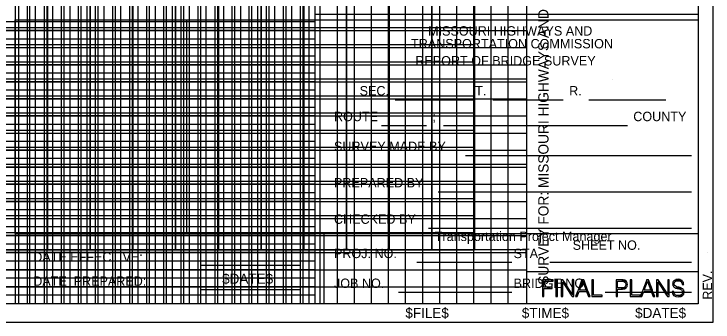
# Model space of a CAD drawing. Extents: x 0 to 31.6, y 0 to 20.8.
# Drawn here: x 23.41 to 31.6, y 0 to 3.61 of the extents above; entities that cross this region are included whole.
import ezdxf

# ---------------------------------------------------------------- set-up
doc = ezdxf.new("R2010")
doc.units = 0
for name, color, linetype in [('Border-Border', 7, 'Continuous'), ('Border-Bridge survey title block', 7, 'Continuous'), ('Border-Bridge xsection major grid lines', 7, 'Continuous'), ('Border-Bridge xsection minor grid lines', 7, 'Continuous'), ('Border-Construction Final Plans Stamp', 7, 'Continuous'), ('Border-Date stamp', 7, 'Continuous'), ('Border-File stamp', 7, 'Continuous'), ('Border-Full plan shape', 7, 'Continuous'), ('Border-Full profile major grid lines', 7, 'Continuous'), ('Border-Full profile minor grid lines', 7, 'Continuous'), ('Border-Full profile shape', 7, 'Continuous'), ('Border-Full xsection major grid lines', 7, 'Continuous'), ('Border-Full xsection minor grid lines', 7, 'Continuous'), ('Border-Plan bottom shape', 7, 'Continuous'), ('Border-Plan-profile major grid lines', 7, 'Continuous'), ('Border-Plan-profile minor grid lines', 7, 'Continuous'), ('Border-Plotting block', 7, 'Continuous'), ('Border-Profile bottom shape', 7, 'Continuous'), ('Border-Revision note', 7, 'Continuous'), ('Border-Time stamp', 7, 'Continuous'), ('Border-Title block - Final Plans Consultant Manual Seal', 7, 'Continuous'), ('Border-Title block - Final Plans Electronic Seal', 7, 'Continuous'), ('Border-Title block - Location Survey Electronic Seal', 7, 'Continuous'), ('Border-Title block - Standard Plans Electronic Seal', 7, 'Continuous'), ('Border-Xsection shape', 7, 'Continuous')]:
    doc.layers.add(name, color=color, linetype=linetype)

msp = doc.modelspace()

# ---------------------------------------------------------------- linework, layer by layer
at = {"layer": 'Border-Border'}
for p, q in [((31.425, 20.5875), (31.425, 0.2125)), ((31.425, 0.2125), (0.175, 0.2125)), ((31.5999, 0), (31.5999, 0))]:
    msp.add_line(p, q, dxfattribs=at)
at = {"layer": 'Border-Bridge survey title block'}
for p, q in [((26.9414, 3.6031), (31.4249, 3.6031)), ((27.8783, 2.6015), (28.7934, 2.6015)), ((29.02, 2.6015), (29.8454, 2.6015)), ((30.1465, 2.6015), (31.047, 2.6015)), ((27.7184, 2.3007), (28.2439, 2.3007)), ((28.4439, 2.3007), (30.5966, 2.3007)), ((28.7003, 1.9511), (31.3478, 1.9511)), ((28.3806, 1.5251), (31.3478, 1.5251)), ((28.2664, 1.0991), (31.3478, 1.0991)), ((28.1294, 0.6991), (29.2454, 0.6991)), ((29.6898, 0.6991), (31.3478, 0.6991)), ((27.9164, 0.3479), (29.2454, 0.3479)), ((30.3368, 0.3479), (31.3478, 0.3479))]:
    msp.add_line(p, q, dxfattribs=at)
msp.add_lwpolyline([(26.9414, 0.2125), (26.9414, 4.2047), (31.4249, 4.2047)], dxfattribs=at)
at = {"layer": 'Border-Bridge xsection major grid lines'}
for p, q in [((23.665, 0.2125), (23.665, 20.5875)), ((24.665, 0.2125), (24.665, 20.5875)), ((25.6649, 0.2125), (25.6649, 20.5875)), ((26.6649, 0.2125), (26.6649, 20.5875)), ((0.175, 3.2125), (26.9415, 3.2125)), ((0.175, 2.2125), (26.9415, 2.2125)), ((0.175, 1.2125), (26.9415, 1.2125))]:
    msp.add_line(p, q, dxfattribs=at)
at = {"layer": 'Border-Bridge xsection minor grid lines'}
for p, q in [((23.465, 20.5875), (23.465, 0.2125)), ((23.565, 20.5875), (23.565, 0.2125)), ((23.765, 20.5875), (23.765, 0.2125)), ((23.865, 20.5875), (23.865, 0.2125)), ((23.965, 20.5875), (23.965, 0.2125)), ((24.065, 20.5875), (24.065, 0.2125)), ((24.165, 20.5875), (24.165, 0.2125)), ((24.265, 20.5875), (24.265, 0.2125)), ((24.365, 20.5875), (24.365, 0.2125)), ((24.465, 20.5875), (24.465, 0.2125)), ((24.565, 20.5875), (24.565, 0.2125)), ((24.765, 20.5875), (24.765, 0.2125)), ((24.865, 20.5875), (24.865, 0.2125)), ((24.965, 20.5875), (24.965, 0.2125)), ((25.0649, 20.5875), (25.0649, 0.2125)), ((25.1649, 20.5875), (25.1649, 0.2125)), ((25.2649, 20.5875), (25.2649, 0.2125)), ((25.3649, 20.5875), (25.3649, 0.2125)), ((25.4649, 20.5875), (25.4649, 0.2125)), ((25.5649, 20.5875), (25.5649, 0.2125)), ((25.7649, 20.5875), (25.7649, 0.2125)), ((25.8649, 20.5875), (25.8649, 0.2125)), ((25.9649, 20.5875), (25.9649, 0.2125)), ((26.0649, 20.5875), (26.0649, 0.2125)), ((26.1649, 20.5875), (26.1649, 0.2125)), ((26.2649, 20.5875), (26.2649, 0.2125)), ((26.3649, 20.5875), (26.3649, 0.2125)), ((26.4649, 20.5875), (26.4649, 0.2125)), ((26.5649, 20.5875), (26.5649, 0.2125)), ((26.7649, 20.5875), (26.7649, 0.2125)), ((26.8649, 20.5875), (26.8649, 0.2125)), ((26.9415, 3.5125), (0.175, 3.5125)), ((26.9415, 3.4125), (0.175, 3.4125)), ((26.9415, 3.3125), (0.175, 3.3125)), ((26.9415, 3.1125), (0.175, 3.1125)), ((26.9415, 3.0125), (0.175, 3.0125)), ((26.9415, 2.9125), (0.175, 2.9125)), ((26.9415, 2.8125), (0.175, 2.8125)), ((26.9415, 2.7125), (0.175, 2.7125)), ((26.9415, 2.6125), (0.175, 2.6125)), ((26.9415, 2.5125), (0.175, 2.5125)), ((26.9415, 2.4125), (0.175, 2.4125)), ((26.9415, 2.3125), (0.175, 2.3125)), ((26.9415, 2.1125), (0.175, 2.1125)), ((26.9415, 2.0125), (0.175, 2.0125)), ((26.9415, 1.9125), (0.175, 1.9125)), ((26.9415, 1.8125), (0.175, 1.8125)), ((26.9415, 1.7125), (0.175, 1.7125)), ((26.9415, 1.6125), (0.175, 1.6125)), ((26.9415, 1.5125), (0.175, 1.5125)), ((26.9415, 1.4125), (0.175, 1.4125)), ((26.9415, 1.3125), (0.175, 1.3125)), ((26.9415, 1.1125), (0.175, 1.1125)), ((26.9415, 1.0125), (0.175, 1.0125)), ((26.9415, 0.9125), (0.175, 0.9125)), ((26.9415, 0.8125), (0.175, 0.8125)), ((26.9415, 0.7125), (0.175, 0.7125)), ((26.9415, 0.6125), (0.175, 0.6125)), ((26.9415, 0.5125), (0.175, 0.5125)), ((26.9415, 0.4125), (0.175, 0.4125)), ((26.9415, 0.3125), (0.175, 0.3125))]:
    msp.add_line(p, q, dxfattribs=at)
at = {"layer": 'Border-Construction Final Plans Stamp'}
msp.add_line((29.4171, 0.5925), (31.4249, 0.5925), dxfattribs=at)
for points in [[(29.6017, 0.3913), (29.6017, 0.2983), (29.6199, 0.2983), (29.6199, 0.3913), (29.716, 0.3913), (29.716, 0.4074), (29.6199, 0.4074), (29.6199, 0.4783), (29.7258, 0.4783), (29.7258, 0.4943), (29.6017, 0.4943), (29.6017, 0.4783), (29.6017, 0.4074)], [(29.758, 0.4943), (29.758, 0.2983), (29.7765, 0.2983), (29.7765, 0.4943)], [(29.8215, 0.3262), (29.8215, 0.2983), (29.8392, 0.2983), (29.8392, 0.3262), (29.8392, 0.4665), (29.8596, 0.4665), (29.8414, 0.4943), (29.8215, 0.4943), (29.8215, 0.4665)], [(29.952, 0.4943), (29.952, 0.3262), (29.9697, 0.3262), (29.9697, 0.4943)], [(30.0132, 0.3587), (29.9903, 0.2983), (30.009, 0.2983), (30.0315, 0.3587), (30.1377, 0.3587), (30.1317, 0.3744), (30.0373, 0.3744), (30.0754, 0.4754), (30.0933, 0.4754), (30.0862, 0.4943), (30.0647, 0.4943), (30.0575, 0.4754), (30.0192, 0.3744)], [(30.1813, 0.3143), (30.1813, 0.2983), (30.3, 0.2983), (30.3, 0.3143), (30.1998, 0.3143), (30.1998, 0.4943), (30.1813, 0.4943)], [(30.4647, 0.3834), (30.4647, 0.2983), (30.4828, 0.2983), (30.4828, 0.3834), (30.5245, 0.3834), (30.5391, 0.3839), (30.5619, 0.3879), (30.5812, 0.3987), (30.582, 0.3998), (30.4828, 0.3998), (30.4828, 0.3999), (30.4828, 0.4015), (30.4828, 0.4086), (30.4828, 0.4168), (30.4828, 0.4228), (30.4828, 0.4394), (30.4828, 0.4396), (30.4828, 0.4557), (30.4828, 0.4598), (30.4828, 0.4682), (30.4828, 0.4757), (30.4828, 0.4774), (30.4828, 0.4779), (30.4828, 0.4783), (30.5834, 0.4783), (30.5671, 0.4893), (30.5474, 0.4937), (30.5333, 0.4943), (30.4647, 0.4943), (30.4647, 0.4937), (30.4647, 0.4893), (30.4647, 0.4783), (30.4647, 0.4779), (30.4647, 0.4774), (30.4647, 0.4757), (30.4647, 0.4682), (30.4647, 0.4598), (30.4647, 0.4557), (30.4647, 0.4396), (30.4647, 0.4394), (30.4647, 0.4228), (30.4647, 0.4168), (30.4647, 0.4086), (30.4647, 0.4015), (30.4647, 0.3999), (30.4647, 0.3998), (30.4647, 0.3987), (30.4647, 0.3879), (30.4647, 0.3839)], [(30.6295, 0.3143), (30.6295, 0.2983), (30.7482, 0.2983), (30.7482, 0.3143), (30.648, 0.3143), (30.648, 0.4943), (30.6295, 0.4943)], [(30.7711, 0.3587), (30.7482, 0.2983), (30.7669, 0.2983), (30.7894, 0.3587), (30.8956, 0.3587), (30.8896, 0.3744), (30.7952, 0.3744), (30.8333, 0.4754), (30.8512, 0.4754), (30.8441, 0.4943), (30.8226, 0.4943), (30.8154, 0.4754), (30.7771, 0.3744)], [(30.9392, 0.3262), (30.9392, 0.2983), (30.9569, 0.2983), (30.9569, 0.3262), (30.9569, 0.4665), (30.9774, 0.4665), (30.9591, 0.4943), (30.9392, 0.4943), (30.9392, 0.4665)], [(31.0697, 0.4943), (31.0697, 0.3262), (31.0874, 0.3262), (31.0874, 0.4943)], [(31.1443, 0.4851), (31.1434, 0.4846), (31.2378, 0.4846), (31.2374, 0.4851), (31.2175, 0.4957), (31.2149, 0.4961), (31.1643, 0.4961), (31.1636, 0.4957)], [(31.1906, 0.4997), (31.1643, 0.4961), (31.2149, 0.4961)], [(29.9314, 0.3262), (29.9498, 0.2983), (29.9697, 0.2983), (29.9697, 0.3262), (29.952, 0.3262), (29.8597, 0.4665), (29.8392, 0.4665)], [(30.0754, 0.4754), (30.1135, 0.3744), (30.1317, 0.3744), (30.0934, 0.4754)], [(30.5324, 0.4783), (30.5394, 0.4779), (30.5839, 0.4779), (30.5834, 0.4783)], [(30.5657, 0.4086), (30.5497, 0.4015), (30.5831, 0.4015), (30.588, 0.4086), (30.5936, 0.4168), (30.5947, 0.4228), (30.5946, 0.4228), (30.5976, 0.4394), (30.5976, 0.4396), (30.5954, 0.4557), (30.5949, 0.4598), (30.59, 0.4682), (30.5856, 0.4757), (30.5846, 0.4774), (30.5839, 0.4779), (30.5394, 0.4779), (30.5428, 0.4774), (30.5544, 0.4757), (30.5686, 0.4682), (30.5741, 0.4598), (30.5767, 0.4557), (30.5791, 0.4396), (30.5791, 0.4394), (30.5762, 0.4228), (30.5718, 0.4168)], [(30.8333, 0.4754), (30.8714, 0.3744), (30.8896, 0.3744), (30.8513, 0.4754)], [(31.0492, 0.3262), (31.0675, 0.2983), (31.0874, 0.2983), (31.0874, 0.3262), (31.0697, 0.3262), (30.9774, 0.4665), (30.9569, 0.4665)], [(31.1654, 0.3978), (31.1677, 0.3969), (31.2311, 0.3969), (31.2296, 0.3978), (31.2145, 0.4031), (31.2144, 0.4031), (31.2128, 0.4037), (31.2007, 0.4071), (31.1779, 0.4129), (31.1752, 0.4137), (31.1671, 0.4161), (31.1548, 0.4228), (31.1503, 0.4286), (31.1471, 0.4328), (31.1457, 0.4397), (31.1445, 0.4462), (31.1445, 0.4464), (31.1445, 0.4469), (31.1446, 0.4474), (31.1467, 0.4596), (31.1469, 0.4611), (31.151, 0.4668), (31.1515, 0.4674), (31.1515, 0.4674), (31.1551, 0.4724), (31.1555, 0.473), (31.1703, 0.481), (31.1709, 0.4814), (31.1897, 0.4836), (31.2385, 0.4836), (31.2378, 0.4846), (31.1434, 0.4846), (31.1427, 0.4836), (31.141, 0.4814), (31.1408, 0.481), (31.135, 0.473), (31.1346, 0.4724), (31.1309, 0.4674), (31.1305, 0.4668), (31.1294, 0.4611), (31.1291, 0.4596), (31.1267, 0.4474), (31.1266, 0.4469), (31.1267, 0.4464), (31.1267, 0.4462), (31.1276, 0.4397), (31.1286, 0.4328), (31.1292, 0.4286), (31.1325, 0.4228), (31.1365, 0.4161), (31.1379, 0.4137), (31.139, 0.4129), (31.1464, 0.4071), (31.1508, 0.4037), (31.1515, 0.4031)], [(31.238, 0.4462), (31.2384, 0.4397), (31.2565, 0.4397), (31.2561, 0.4462), (31.2561, 0.4464), (31.2561, 0.4469), (31.2561, 0.4474), (31.2528, 0.4596), (31.2528, 0.4596), (31.2524, 0.4611), (31.2509, 0.4668), (31.2507, 0.4674), (31.2469, 0.4724), (31.2465, 0.473), (31.2404, 0.481), (31.2402, 0.4814), (31.2402, 0.4814), (31.2385, 0.4836), (31.1897, 0.4836), (31.2063, 0.4814), (31.2086, 0.481), (31.2239, 0.473), (31.225, 0.4724), (31.2287, 0.4674), (31.2291, 0.4668), (31.2332, 0.4611), (31.2343, 0.4596), (31.2377, 0.4474), (31.2378, 0.4469), (31.2379, 0.4464)], [(30.1194, 0.3587), (30.1418, 0.2983), (30.1606, 0.2983), (30.1377, 0.3587)], [(30.5323, 0.3999), (30.5248, 0.3998), (30.582, 0.3998), (30.582, 0.3999)], [(30.5496, 0.4015), (30.5324, 0.3999), (30.582, 0.3999), (30.5831, 0.4015)], [(30.8772, 0.3587), (30.8997, 0.2983), (30.9185, 0.2983), (30.8956, 0.3587)], [(31.1647, 0.2968), (31.1947, 0.293), (31.2202, 0.2968), (31.224, 0.2974), (31.2444, 0.309), (31.195, 0.309), (31.1924, 0.3093), (31.186, 0.3101), (31.1753, 0.3113), (31.174, 0.3119), (31.1585, 0.3186), (31.1553, 0.3221), (31.1498, 0.3279), (31.1498, 0.3279), (31.1471, 0.3308), (31.1459, 0.3322), (31.1442, 0.337), (31.1408, 0.3468), (31.1404, 0.3502), (31.1403, 0.3517), (31.1398, 0.3577), (31.1217, 0.3577), (31.1219, 0.3517), (31.122, 0.3502), (31.1227, 0.3468), (31.1246, 0.337), (31.1255, 0.3322), (31.1258, 0.3308), (31.1278, 0.3279), (31.1319, 0.3221), (31.1343, 0.3186), (31.139, 0.3119), (31.1395, 0.3113), (31.1403, 0.3101), (31.1409, 0.3093), (31.1415, 0.309), (31.1636, 0.2974)], [(31.1974, 0.3093), (31.195, 0.309), (31.2444, 0.309), (31.2449, 0.3093), (31.2462, 0.3101), (31.2471, 0.3113), (31.2475, 0.3119), (31.2521, 0.3186), (31.2545, 0.3221), (31.2585, 0.3279), (31.2589, 0.3308), (31.2589, 0.3308), (31.2591, 0.3322), (31.2598, 0.337), (31.2613, 0.3468), (31.2618, 0.3502), (31.2621, 0.3517), (31.2592, 0.3661), (31.2579, 0.3723), (31.2541, 0.3771), (31.2484, 0.3846), (31.2458, 0.3879), (31.2439, 0.3891), (31.2439, 0.3891), (31.2361, 0.3938), (31.2311, 0.3969), (31.1677, 0.3969), (31.1796, 0.3938), (31.1982, 0.3891), (31.2022, 0.3879), (31.2142, 0.3846), (31.2302, 0.3771), (31.2346, 0.3723), (31.2402, 0.3661), (31.2438, 0.3517), (31.2437, 0.3502), (31.2434, 0.3468), (31.2427, 0.337), (31.2399, 0.3322), (31.2391, 0.3308), (31.2374, 0.3279), (31.2341, 0.3221), (31.2281, 0.3186), (31.2166, 0.3119), (31.2124, 0.3113), (31.203, 0.3101)]]:
    msp.add_lwpolyline(points, close=True, dxfattribs=at)
at = {"layer": 'Border-Full plan shape'}
msp.add_lwpolyline([(0.8061, 19.9564), (28.8061, 19.9564), (28.8061, 0.8436), (0.8061, 0.8436)], close=True, dxfattribs=at)
at = {"layer": 'Border-Full profile major grid lines'}
for p, q in [((23.8061, 19.8436), (23.8061, 0.8436)), ((24.8061, 19.8436), (24.8061, 0.8436)), ((25.8061, 19.8436), (25.8061, 0.8436)), ((26.8061, 19.8436), (26.8061, 0.8436)), ((27.8061, 19.8436), (27.8061, 0.8436)), ((28.8061, 19.8436), (28.8061, 0.8436)), ((29.4171, 2.8436), (0.175, 2.8436)), ((29.4171, 1.8436), (0.175, 1.8436)), ((29.4171, 0.8436), (0.175, 0.8436))]:
    msp.add_line(p, q, dxfattribs=at)
at = {"layer": 'Border-Full profile minor grid lines'}
for p, q in [((24.3061, 19.8436), (24.3061, 0.8436)), ((25.3061, 19.8436), (25.3061, 0.8436)), ((26.3061, 19.8436), (26.3061, 0.8436)), ((27.3061, 19.8436), (27.3061, 0.8436)), ((28.3061, 19.8436), (28.3061, 0.8436)), ((28.8061, 3.4436), (0.8061, 3.4436)), ((28.8061, 3.2436), (0.8061, 3.2436)), ((28.8061, 3.0436), (0.8061, 3.0436)), ((28.8061, 2.6436), (0.8061, 2.6436)), ((28.8061, 2.4436), (0.8061, 2.4436)), ((28.8061, 2.2436), (0.8061, 2.2436)), ((28.8061, 2.0436), (0.8061, 2.0436)), ((28.8061, 1.6436), (0.8061, 1.6436)), ((28.8061, 1.4436), (0.8061, 1.4436)), ((28.8061, 1.2436), (0.8061, 1.2436)), ((28.8061, 1.0436), (0.8061, 1.0436))]:
    msp.add_line(p, q, dxfattribs=at)
at = {"layer": 'Border-Full profile shape'}
msp.add_lwpolyline([(0.8061, 19.9564), (28.8061, 19.9564), (28.8061, 0.8436), (0.8061, 0.8436)], close=True, dxfattribs=at)
at = {"layer": 'Border-Full xsection major grid lines'}
for p, q in [((23.8, 0.2125), (23.8, 20.5875)), ((24.8, 0.2125), (24.8, 20.5875)), ((25.7999, 0.2125), (25.7999, 20.5875)), ((26.7999, 0.2125), (26.7999, 20.5875)), ((27.7999, 0.2125), (27.7999, 20.5875)), ((28.7999, 0.2125), (28.7999, 20.5875)), ((0.175, 3.2125), (29.4171, 3.2125)), ((0.175, 2.2125), (29.4171, 2.2125)), ((0.175, 1.2125), (29.4171, 1.2125))]:
    msp.add_line(p, q, dxfattribs=at)
at = {"layer": 'Border-Full xsection minor grid lines'}
for p, q in [((23.6, 0.2125), (23.6, 20.5875)), ((24, 0.2125), (24, 20.5875)), ((24.2, 0.2125), (24.2, 20.5875)), ((24.4, 0.2125), (24.4, 20.5875)), ((24.6, 0.2125), (24.6, 20.5875)), ((24.9999, 0.2125), (24.9999, 20.5875)), ((25.1999, 0.2125), (25.1999, 20.5875)), ((25.3999, 0.2125), (25.3999, 20.5875)), ((25.5999, 0.2125), (25.5999, 20.5875)), ((25.9999, 0.2125), (25.9999, 20.5875)), ((26.1999, 0.2125), (26.1999, 20.5875)), ((26.3999, 0.2125), (26.3999, 20.5875)), ((26.5999, 0.2125), (26.5999, 20.5875)), ((26.9999, 0.2125), (26.9999, 20.5875)), ((27.1999, 0.2125), (27.1999, 20.5875)), ((27.3999, 0.2125), (27.3999, 20.5875)), ((27.5999, 0.2125), (27.5999, 20.5875)), ((27.9999, 0.2125), (27.9999, 20.5875)), ((28.1999, 0.2125), (28.1999, 20.5875)), ((28.3999, 0.2125), (28.3999, 20.5875)), ((28.5999, 0.2125), (28.5999, 20.5875)), ((28.9999, 0.2125), (28.9999, 20.5875)), ((29.1999, 0.2125), (29.1999, 20.5875)), ((0.175, 3.4125), (29.4171, 3.4125)), ((0.175, 3.0125), (29.4171, 3.0125)), ((0.175, 2.8125), (29.4171, 2.8125)), ((0.175, 2.6125), (29.4171, 2.6125)), ((0.175, 2.4125), (29.4171, 2.4125)), ((0.175, 2.0125), (29.4171, 2.0125)), ((0.175, 1.8125), (29.4171, 1.8125)), ((0.175, 1.6125), (29.4171, 1.6125)), ((0.175, 1.4125), (29.4171, 1.4125)), ((0.175, 1.0125), (29.4171, 1.0125)), ((0.175, 0.8125), (29.4171, 0.8125)), ((0.175, 0.6125), (29.4171, 0.6125)), ((0.175, 0.4125), (29.4171, 0.4125))]:
    msp.add_line(p, q, dxfattribs=at)
at = {"layer": 'Border-Plan bottom shape'}
msp.add_lwpolyline([(0.8061, 10.3253), (28.8061, 10.3253), (28.8061, 0.8436), (0.8061, 0.8436)], close=True, dxfattribs=at)
at = {"layer": 'Border-Plan-profile major grid lines'}
for p, q in [((23.8061, 0.8436), (23.8061, 9.8436)), ((24.8061, 0.8436), (24.8061, 9.8436)), ((25.8061, 0.8436), (25.8061, 9.8436)), ((26.8061, 0.8436), (26.8061, 9.8436)), ((27.8061, 0.8436), (27.8061, 9.8436)), ((28.8061, 0.8436), (28.8061, 9.8436)), ((29.4233, 2.8436), (0.1811, 2.8436)), ((29.4233, 1.8436), (0.1811, 1.8436)), ((29.4233, 0.8436), (0.1811, 0.8436))]:
    msp.add_line(p, q, dxfattribs=at)
at = {"layer": 'Border-Plan-profile minor grid lines'}
for p, q in [((24.3061, 0.8436), (24.3061, 9.8436)), ((25.3061, 0.8436), (25.3061, 9.8436)), ((26.3061, 0.8436), (26.3061, 9.8436)), ((27.3061, 0.8436), (27.3061, 9.8436)), ((28.3061, 0.8436), (28.3061, 9.8436)), ((28.8061, 3.4436), (0.8061, 3.4436)), ((28.8061, 3.2436), (0.8061, 3.2436)), ((28.8061, 3.0436), (0.8061, 3.0436)), ((28.8061, 2.6436), (0.8061, 2.6436)), ((28.8061, 2.4436), (0.8061, 2.4436)), ((28.8061, 2.2436), (0.8061, 2.2436)), ((28.8061, 2.0436), (0.8061, 2.0436)), ((28.8061, 1.6436), (0.8061, 1.6436)), ((28.8061, 1.4436), (0.8061, 1.4436)), ((28.8061, 1.2436), (0.8061, 1.2436)), ((28.8061, 1.0436), (0.8061, 1.0436))]:
    msp.add_line(p, q, dxfattribs=at)
at = {"layer": 'Border-Plotting block'}
msp.add_lwpolyline([(0, 0), (31.5999, 0), (31.5999, 20.8), (0, 20.8)], close=True, dxfattribs=at)
at = {"layer": 'Border-Profile bottom shape'}
msp.add_lwpolyline([(0.8061, 0.8436), (28.8061, 0.8436), (28.8061, 9.8436), (0.8061, 9.8436)], close=True, dxfattribs=at)
at = {"layer": 'Border-Revision note'}
msp.add_line((31.5347, 0.8092), (31.5347, 0.8092), dxfattribs=at)
at = {"layer": 'Border-Title block - Final Plans Consultant Manual Seal'}
msp.add_line((29.4171, 20.5875), (29.4171, 0.2125), dxfattribs=at)
at = {"layer": 'Border-Title block - Final Plans Electronic Seal'}
for p, q in [((29.4171, 20.5875), (29.4171, 0.2125)), ((30.4211, 2.8362), (30.4211, 2.8362))]:
    msp.add_line(p, q, dxfattribs=at)
at = {"layer": 'Border-Title block - Location Survey Electronic Seal'}
msp.add_line((29.4171, 20.5875), (29.4171, 0.2125), dxfattribs=at)
at = {"layer": 'Border-Title block - Standard Plans Electronic Seal'}
for p, q in [((23.4249, 4.8718), (23.4249, 0.2125)), ((23.4249, 3.5375), (31.425, 3.5375)), ((25.4328, 3.5375), (25.4328, 1.0375)), ((23.4249, 1.0375), (31.425, 1.0375)), ((27.0397, 1.0375), (27.0397, 0.2125)), ((29.4171, 1.0375), (29.4171, 0.2125)), ((25.6068, 0.6651), (26.7737, 0.6651)), ((25.6068, 0.3818), (26.7737, 0.3818))]:
    msp.add_line(p, q, dxfattribs=at)
msp.add_lwpolyline([(23.4249, 3.5375), (25.4328, 3.5375), (25.4328, 1.0375), (23.4249, 1.0375)], close=True, dxfattribs=at)
at = {"layer": 'Border-Xsection shape'}
msp.add_lwpolyline([(29.4171, 0.2125), (0.175, 0.2125), (0.175, 20.5875), (29.4171, 20.5875)], close=True, dxfattribs=at)

# ---------------------------------------------------------------- texts
at = {"layer": 'Border-Bridge survey title block'}
for s, height, p in [('MISSOURI HIGHWAYS AND', 0.110166, (28.2628, 3.3527)), ('TRANSPORTATION COMMISSION', 0.110192, (28.0628, 3.2031)), ('REPORT OF BRIDGE SURVEY', 0.110192, (28.1131, 3.0031)), ('SEC.', 0.11019, (27.4612, 2.6518)), ('T.', 0.11019, (28.8139, 2.6518)), ('R.', 0.11019, (29.9147, 2.6518)), ('ROUTE', 0.11019, (27.1604, 2.3511)), ('COUNTY', 0.11019, (30.6659, 2.3511)), (';', 0.1102, (28.3131, 2.3511)), ('SURVEY MADE BY', 0.110192, (27.1604, 2.0015)), ('PREPARED BY', 0.110166, (27.1604, 1.5755)), ('CHECKED BY', 0.11019, (27.1604, 1.1495)), ('Transportation Project Manager', 0.110166, (28.3409, 0.948)), ('PROJ. NO.', 0.11019, (27.1604, 0.7479)), ('STA.', 0.11019, (29.2643, 0.7479)), ('JOB NO.', 0.11019, (27.1604, 0.3983)), ('BRIDGE NO.', 0.11019, (29.2643, 0.3983))]:
    msp.add_text(s, height=height, dxfattribs=at).set_placement(p)
at = {"layer": 'Border-Date stamp'}
msp.add_text('$DATE$', height=0.11811, dxfattribs=at).set_placement((30.6876, 0.0472))
at = {"layer": 'Border-File stamp'}
msp.add_text('$FILE$', height=0.11811, dxfattribs=at).set_placement((27.9962, 0.0472))
at = {"layer": 'Border-Revision note'}
msp.add_text('REV.', height=0.10827, rotation=90, dxfattribs=at).set_placement((31.5888, 0.263))
at = {"layer": 'Border-Time stamp'}
msp.add_text('$TIME$', height=0.11811, dxfattribs=at).set_placement((29.3609, 0.0472))
at = {"layer": 'Border-Title block - Location Survey Electronic Seal'}
msp.add_text('SURVEY FOR: MISSOURI HIGHWAYS AND TRANSPORTATION COMMISSION', height=0.12, rotation=90, dxfattribs=at).set_placement((29.6734, 0.4356))
at = {"layer": 'Border-Title block - Standard Plans Electronic Seal'}
for s, height, p in [('SHEET NO.', 0.11, (29.9561, 0.845)), ('DATE EFFECTIVE:', 0.11, (23.6381, 0.7063)), ('$DATE$', 0.11811, (25.8509, 0.4474)), ('DATE  PREPARED:', 0.11, (23.6381, 0.4237))]:
    msp.add_text(s, height=height, dxfattribs=at).set_placement(p)

doc.saveas('drawing.dxf')
